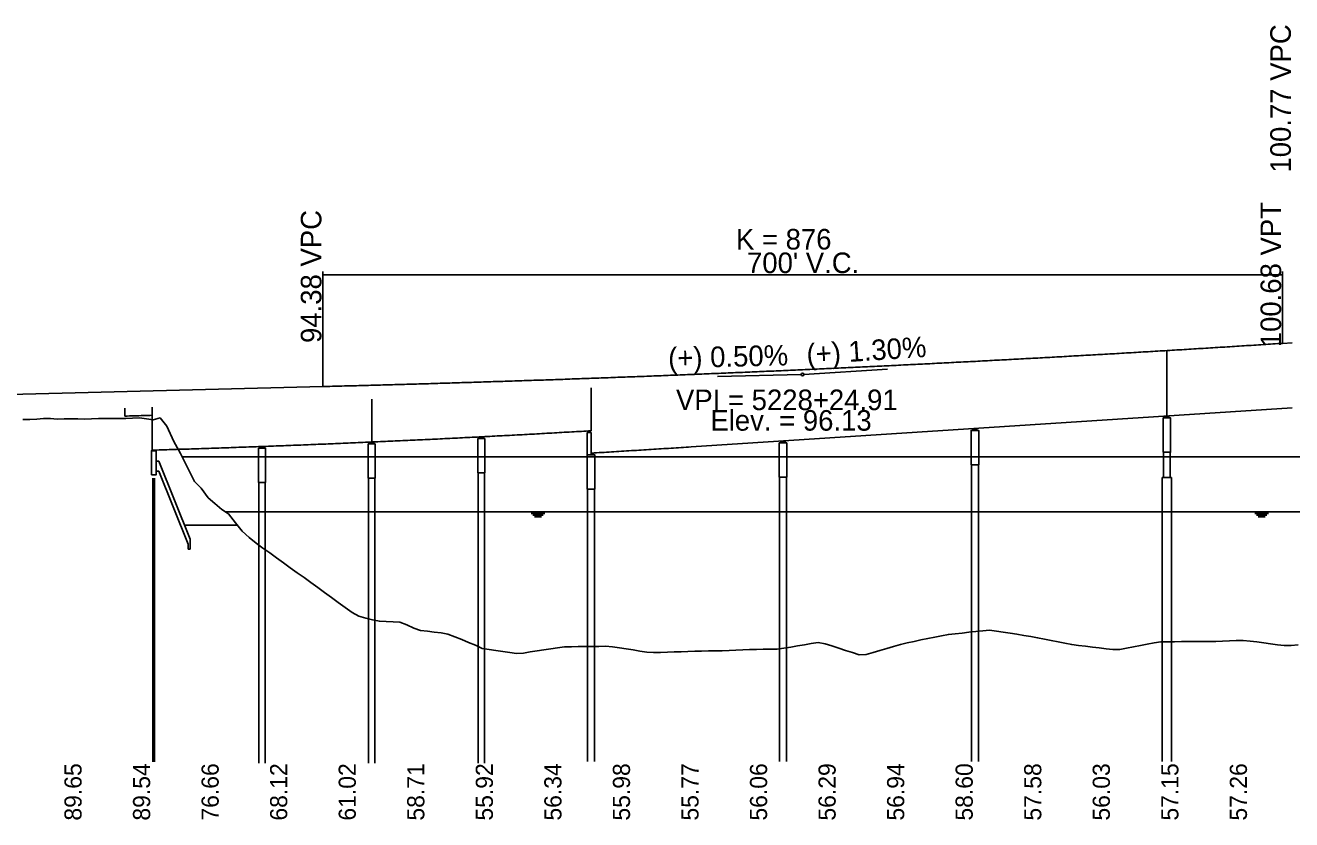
# Model space of a CAD drawing. Extents: x 2121671 to 2169879, y 557274 to 599957.
# Drawn here: x 2151826 to 2152750, y 595763 to 596343 of the extents above; entities that cross this region are included whole.
import ezdxf

# ---------------------------------------------------------------- set-up
doc = ezdxf.new("R2010")
doc.units = 0
for name, color, linetype in [('BR_CONCRETE', 7, 'Continuous'), ('BR_DETAILS', 7, 'Continuous'), ('BR_PRESTRESSED BEAM', 7, 'Continuous'), ('BR_STRUCTURAL STEEL', 7, 'Continuous'), ('RD_DDB_GradeTX', 7, 'Continuous'), ('RD_DDB_Profile_Elev', 7, 'Continuous'), ('RD_DDB_Profile_EX', 7, 'Continuous'), ('RD_DDB_Profile_Lbl', 7, 'Continuous'), ('RD_DDB_Profile_PR', 7, 'Continuous'), ('RD_DDB_StripGrade', 7, 'Continuous'), ('RD_DDB_VCLbl', 7, 'Continuous')]:
    doc.layers.add(name, color=color, linetype=linetype)

msp = doc.modelspace()

# ---------------------------------------------------------------- linework, layer by layer
at = {"layer": 'BR_CONCRETE'}
for p, q in [((2151898.82, 596063.63), (2151898.82, 596057.79)), ((2151898.82, 596063.63), (2151898.82, 596057.79)), ((2152236.07, 596029.6), (2152236.07, 596045.79)), ((2152236.07, 596045.79), (2152238.82, 596045.79)), ((2152236.07, 596029.6), (2152236.07, 596045.79)), ((2152236.07, 596045.79), (2152238.82, 596045.79)), ((2152238.82, 596045.79), (2152238.82, 596029.6)), ((2152238.82, 596045.79), (2152238.82, 596029.6)), ((2152656.32, 596031.43), (2152656.32, 596013.07)), ((2152656.32, 596031.43), (2152656.32, 596013.07)), ((2152661.32, 596031.43), (2152661.32, 596013.07)), ((2152661.32, 596031.43), (2152661.32, 596013.07)), ((2152516.32, 596022.33), (2152516.32, 596013.07)), ((2152516.32, 596022.33), (2152516.32, 596013.07)), ((2152521.32, 596022.33), (2152521.32, 596013.07)), ((2152521.32, 596022.33), (2152521.32, 596013.07)), ((2152076.57, 596012.55), (2152076.57, 595804.68)), ((2152076.57, 596012.55), (2152076.57, 595804.68)), ((2152081.07, 596012.55), (2152081.07, 595804.68)), ((2152081.07, 596012.55), (2152081.07, 595804.68)), ((2152156.57, 596016.35), (2152156.57, 595804.69)), ((2152156.57, 596016.35), (2152156.57, 595804.69)), ((2152161.07, 596016.35), (2152161.07, 595804.69)), ((2152161.07, 596016.35), (2152161.07, 595804.69)), ((2152376.32, 596013.23), (2152376.32, 596013.07)), ((2152376.32, 596013.23), (2152376.32, 596013.07)), ((2152376.32, 596013.07), (2152376.32, 595805.78)), ((2152376.32, 596013.07), (2152376.32, 595805.78)), ((2152381.32, 596013.23), (2152381.32, 596013.07)), ((2152381.32, 596013.23), (2152381.32, 596013.07)), ((2152381.32, 596013.07), (2152381.32, 595805.78)), ((2152381.32, 596013.07), (2152381.32, 595805.78)), ((2152516.32, 596013.07), (2152516.32, 595805.78)), ((2152516.32, 596013.07), (2152516.32, 595805.78)), ((2152521.32, 596013.07), (2152521.32, 595805.78)), ((2152521.32, 596013.07), (2152521.32, 595805.78)), ((2152655.32, 596013.07), (2152655.32, 595805.78)), ((2152655.32, 596013.07), (2152655.32, 595805.78)), ((2152662.32, 596013.07), (2152662.32, 595805.78)), ((2152662.32, 596013.07), (2152662.32, 595805.78)), ((2151996.57, 596009.32), (2151996.57, 595804.67)), ((2151996.57, 596009.32), (2151996.57, 595804.67)), ((2152001.07, 596009.32), (2152001.07, 595804.67)), ((2152001.07, 596009.32), (2152001.07, 595804.67)), ((2152236.32, 596004.6), (2152236.32, 595805.88)), ((2152236.32, 596004.6), (2152236.32, 595805.88)), ((2152241.32, 596004.6), (2152241.32, 595805.88)), ((2152241.32, 596004.6), (2152241.32, 595805.88))]:
    msp.add_line(p, q, dxfattribs=at)
for points in [[(2152656.07, 596031.43), (2152661.57, 596031.43), (2152661.57, 596056.43), (2152656.07, 596056.43)], [(2152656.07, 596031.43), (2152661.57, 596031.43), (2152661.57, 596056.43), (2152656.07, 596056.43)], [(2152156.32, 596016.35), (2152161.32, 596016.35), (2152161.32, 596041.35), (2152156.32, 596041.35)], [(2152156.32, 596016.35), (2152161.32, 596016.35), (2152161.32, 596041.35), (2152156.32, 596041.35)], [(2152516.07, 596022.33), (2152521.57, 596022.33), (2152521.57, 596047.33), (2152516.07, 596047.33)], [(2152516.07, 596022.33), (2152521.57, 596022.33), (2152521.57, 596047.33), (2152516.07, 596047.33)], [(2151918.16, 596015.05), (2151921.66, 596015.05), (2151921.66, 596032.55), (2151918.16, 596032.55)], [(2151918.16, 596015.05), (2151921.66, 596015.05), (2151921.66, 596032.55), (2151918.16, 596032.55)], [(2151996.32, 596009.32), (2152001.32, 596009.32), (2152001.32, 596034.32), (2151996.32, 596034.32)], [(2151996.32, 596009.32), (2152001.32, 596009.32), (2152001.32, 596034.32), (2151996.32, 596034.32)], [(2152076.32, 596012.55), (2152081.32, 596012.55), (2152081.32, 596037.55), (2152076.32, 596037.55)], [(2152076.32, 596012.55), (2152081.32, 596012.55), (2152081.32, 596037.55), (2152076.32, 596037.55)], [(2152236.07, 596004.6), (2152241.57, 596004.6), (2152241.57, 596029.6), (2152236.07, 596029.6)], [(2152236.07, 596004.6), (2152241.57, 596004.6), (2152241.57, 596029.6), (2152236.07, 596029.6)], [(2152376.07, 596013.23), (2152381.57, 596013.23), (2152381.57, 596038.23), (2152376.07, 596038.23)], [(2152376.07, 596013.23), (2152381.57, 596013.23), (2152381.57, 596038.23), (2152376.07, 596038.23)]]:
    msp.add_lwpolyline(points, close=True, dxfattribs=at)
msp.add_spline([(2151898.82, 596057.79), (2151905.74, 596057.99), (2151918.82, 596058.37)], degree=3, dxfattribs=at)
msp.add_spline([(2151898.82, 596057.79), (2151905.74, 596057.99), (2151918.82, 596058.37)], degree=3, dxfattribs=at)
at = {"layer": 'BR_DETAILS'}
for p, q in [((2151921.66, 596025.01), (2151923.66, 596025.01)), ((2151921.66, 596025.01), (2151923.66, 596025.01)), ((2151946.42, 595968.12), (2151923.66, 596025.01)), ((2151946.42, 595968.12), (2151923.66, 596025.01)), ((2151921.66, 596017.51), (2151923.66, 596017.51)), ((2151921.66, 596017.51), (2151923.66, 596017.51)), ((2151944.92, 595964.37), (2151923.66, 596017.51)), ((2151944.92, 595964.37), (2151923.66, 596017.51)), ((2151942.42, 595978.12), (2151980.88, 595978.12)), ((2151942.42, 595978.12), (2151980.88, 595978.12)), ((2151946.42, 595968.12), (2151946.42, 595960.62)), ((2151946.42, 595968.12), (2151946.42, 595960.62)), ((2151944.92, 595960.62), (2151944.92, 595964.37)), ((2151944.92, 595960.62), (2151944.92, 595964.37)), ((2151946.42, 595960.62), (2151944.92, 595960.62)), ((2151946.42, 595960.62), (2151944.92, 595960.62))]:
    msp.add_line(p, q, dxfattribs=at)
for points in [[(2152657.32, 596057.68), (2152658.32, 596057.68), (2152658.32, 596056.43), (2152657.32, 596056.43)], [(2152657.32, 596057.68), (2152658.32, 596057.68), (2152658.32, 596056.43), (2152657.32, 596056.43)], [(2152659.32, 596057.68), (2152660.32, 596057.68), (2152660.32, 596056.43), (2152659.32, 596056.43)], [(2152659.32, 596057.68), (2152660.32, 596057.68), (2152660.32, 596056.43), (2152659.32, 596056.43)], [(2152517.32, 596048.58), (2152518.32, 596048.58), (2152518.32, 596047.33), (2152517.32, 596047.33)], [(2152517.32, 596048.58), (2152518.32, 596048.58), (2152518.32, 596047.33), (2152517.32, 596047.33)], [(2152519.32, 596048.58), (2152520.32, 596048.58), (2152520.32, 596047.33), (2152519.32, 596047.33)], [(2152519.32, 596048.58), (2152520.32, 596048.58), (2152520.32, 596047.33), (2152519.32, 596047.33)], [(2152077.32, 596038.8), (2152078.32, 596038.8), (2152078.32, 596037.55), (2152077.32, 596037.55)], [(2152077.32, 596038.8), (2152078.32, 596038.8), (2152078.32, 596037.55), (2152077.32, 596037.55)], [(2152079.32, 596038.8), (2152080.32, 596038.8), (2152080.32, 596037.55), (2152079.32, 596037.55)], [(2152079.32, 596038.8), (2152080.32, 596038.8), (2152080.32, 596037.55), (2152079.32, 596037.55)], [(2152157.32, 596042.6), (2152158.32, 596042.6), (2152158.32, 596041.35), (2152157.32, 596041.35)], [(2152157.32, 596042.6), (2152158.32, 596042.6), (2152158.32, 596041.35), (2152157.32, 596041.35)], [(2152159.32, 596042.6), (2152160.32, 596042.6), (2152160.32, 596041.35), (2152159.32, 596041.35)], [(2152159.32, 596042.6), (2152160.32, 596042.6), (2152160.32, 596041.35), (2152159.32, 596041.35)], [(2152237.32, 596047.04), (2152238.32, 596047.04), (2152238.32, 596045.79), (2152237.32, 596045.79)], [(2152237.32, 596047.04), (2152238.32, 596047.04), (2152238.32, 596045.79), (2152237.32, 596045.79)], [(2152377.32, 596039.48), (2152378.32, 596039.48), (2152378.32, 596038.23), (2152377.32, 596038.23)], [(2152377.32, 596039.48), (2152378.32, 596039.48), (2152378.32, 596038.23), (2152377.32, 596038.23)], [(2152379.32, 596039.48), (2152380.32, 596039.48), (2152380.32, 596038.23), (2152379.32, 596038.23)], [(2152379.32, 596039.48), (2152380.32, 596039.48), (2152380.32, 596038.23), (2152379.32, 596038.23)], [(2151919.32, 596032.97), (2151920.49, 596032.97), (2151920.49, 596032.55), (2151919.32, 596032.55)], [(2151919.32, 596032.97), (2151920.49, 596032.97), (2151920.49, 596032.55), (2151919.32, 596032.55)], [(2151997.32, 596035.57), (2151998.32, 596035.57), (2151998.32, 596034.32), (2151997.32, 596034.32)], [(2151997.32, 596035.57), (2151998.32, 596035.57), (2151998.32, 596034.32), (2151997.32, 596034.32)], [(2151999.32, 596035.57), (2152000.32, 596035.57), (2152000.32, 596034.32), (2151999.32, 596034.32)], [(2151999.32, 596035.57), (2152000.32, 596035.57), (2152000.32, 596034.32), (2151999.32, 596034.32)], [(2152239.32, 596030.85), (2152240.32, 596030.85), (2152240.32, 596029.6), (2152239.32, 596029.6)], [(2152239.32, 596030.85), (2152240.32, 596030.85), (2152240.32, 596029.6), (2152239.32, 596029.6)]]:
    msp.add_lwpolyline(points, close=True, dxfattribs=at)
at = {"layer": 'BR_PRESTRESSED BEAM'}
for p, q in [((2152658.82, 596057.78), (2152658.82, 596105.28)), ((2152658.82, 596057.78), (2152658.82, 596105.28)), ((2152238.82, 596047.07), (2152238.82, 596078.32)), ((2152238.82, 596047.07), (2152238.82, 596078.32)), ((2152078.82, 596038.86), (2152078.82, 596070.11)), ((2152078.82, 596038.86), (2152078.82, 596070.11)), ((2151918.82, 596064.2), (2151918.82, 596032.95)), ((2151918.82, 596064.2), (2151918.82, 596032.95)), ((2152311.74, 596035.32), (2152750.24, 596063.82)), ((2152311.74, 596035.32), (2152750.24, 596063.82)), ((2152655.32, 596013.07), (2152662.32, 596013.07)), ((2152655.32, 596013.07), (2152662.32, 596013.07))]:
    msp.add_line(p, q, dxfattribs=at)
for points in [[(2151918.82, 596032.95), (2151920.24, 596032.99), (2151934.74, 596033.44), (2151949.24, 596033.9), (2151963.74, 596034.38), (2151978.24, 596034.88), (2151992.74, 596035.4), (2152007.24, 596035.94), (2152021.74, 596036.49), (2152036.24, 596037.07), (2152050.74, 596037.66), (2152065.24, 596038.27), (2152079.74, 596038.9), (2152094.24, 596039.55), (2152108.74, 596040.22), (2152123.24, 596040.91), (2152137.74, 596041.62), (2152152.24, 596042.34), (2152166.74, 596043.09), (2152181.24, 596043.85), (2152195.74, 596044.63), (2152210.24, 596045.44), (2152224.74, 596046.26), (2152238.82, 596047.07)], [(2151918.82, 596032.95), (2151920.24, 596032.99), (2151934.74, 596033.44), (2151949.24, 596033.9), (2151963.74, 596034.38), (2151978.24, 596034.88), (2151992.74, 596035.4), (2152007.24, 596035.94), (2152021.74, 596036.49), (2152036.24, 596037.07), (2152050.74, 596037.66), (2152065.24, 596038.27), (2152079.74, 596038.9), (2152094.24, 596039.55), (2152108.74, 596040.22), (2152123.24, 596040.91), (2152137.74, 596041.62), (2152152.24, 596042.34), (2152166.74, 596043.09), (2152181.24, 596043.85), (2152195.74, 596044.63), (2152210.24, 596045.44), (2152224.74, 596046.26), (2152238.82, 596047.07)], [(2152238.82, 596030.82), (2152239.24, 596030.84), (2152253.74, 596031.7), (2152268.24, 596032.58), (2152282.74, 596033.47), (2152297.24, 596034.39), (2152311.74, 596035.32)], [(2152238.82, 596030.82), (2152239.24, 596030.84), (2152253.74, 596031.7), (2152268.24, 596032.58), (2152282.74, 596033.47), (2152297.24, 596034.39), (2152311.74, 596035.32)]]:
    msp.add_spline(points, degree=3, dxfattribs=at)
at = {"layer": 'BR_STRUCTURAL STEEL'}
for p, q in [((2151919.32, 596012.51), (2151919.32, 595805.58)), ((2151919.32, 596012.51), (2151919.32, 595805.58)), ((2151920.49, 596012.51), (2151920.49, 595805.58)), ((2151920.49, 596012.51), (2151920.49, 595805.58))]:
    msp.add_line(p, q, dxfattribs=at)
at = {"layer": 'RD_DDB_GradeTX'}
for p, q in [((2152331.17, 596086.57), (2152392.16, 596088.09)), ((2152455.02, 596092.14), (2152394.15, 596088.18))]:
    msp.add_line(p, q, dxfattribs=at)
msp.add_circle((2152393.15, 596088.12), 1, dxfattribs=at)
at = {"layer": 'RD_DDB_Profile_Elev'}
for p, q in [((2151940.69, 596028.07), (2155629.71, 596028.07)), ((2151971.97, 595988.07), (2156334.94, 595988.07)), ((2152195.16, 595986.82), (2152205.16, 595986.82)), ((2152196.41, 595985.57), (2152203.91, 595985.57)), ((2152197.66, 595984.32), (2152202.66, 595984.32)), ((2152723, 595986.82), (2152733, 595986.82)), ((2152724.25, 595985.57), (2152731.75, 595985.57)), ((2152725.5, 595984.32), (2152730.5, 595984.32))]:
    msp.add_line(p, q, dxfattribs=at)
at = {"layer": 'RD_DDB_Profile_EX'}
for points in [[(2151824.48, 596055.23), (2151829.48, 596055.31), (2151834.48, 596055.57), (2151839.48, 596055.98), (2151844.48, 596055.98), (2151849.48, 596055.53), (2151854.48, 596055.69), (2151859.48, 596055.83), (2151864.48, 596055.79), (2151869.48, 596055.67), (2151874.48, 596055.78), (2151879.48, 596055.97), (2151884.48, 596056.16), (2151889.48, 596055.98), (2151894.48, 596056.08), (2151899.48, 596056.01), (2151904.48, 596056.23), (2151909.48, 596056.55), (2151914.48, 596055.74), (2151919.48, 596054.96), (2151924.48, 596056.45), (2151929.48, 596050.33), (2151934.48, 596039.19), (2151939.48, 596030.54), (2151944.48, 596020.27), (2151949.48, 596010.09), (2151954.48, 596005.12), (2151959.48, 595998.24), (2151964.48, 595993.98), (2151969.48, 595989.72), (2151974.48, 595986.4), (2151979.48, 595979.81), (2151984.48, 595973.75), (2151989.48, 595969.33), (2151994.48, 595964.99), (2151999.48, 595961.56), (2152004.48, 595958.03), (2152009.48, 595954.42), (2152014.48, 595950.8), (2152019.48, 595947.18), (2152024.48, 595943.57), (2152029.48, 595939.95), (2152034.48, 595936.33), (2152039.48, 595932.72), (2152044.48, 595929.1), (2152049.48, 595925.48), (2152054.48, 595921.87), (2152059.48, 595918.25), (2152064.48, 595914.63), (2152069.48, 595911.89), (2152074.48, 595910.47), (2152079.48, 595909.05), (2152084.48, 595908.12), (2152089.48, 595907.89), (2152094.48, 595907.67), (2152099.48, 595907.44), (2152104.48, 595905.51), (2152109.48, 595903.15), (2152114.48, 595901.46), (2152119.48, 595900.87), (2152124.48, 595900.28), (2152129.48, 595899.69), (2152134.48, 595898.75), (2152139.48, 595896.73), (2152144.48, 595894.72), (2152149.48, 595892.7), (2152154.48, 595890.68), (2152159.48, 595888.34), (2152164.48, 595887.61), (2152169.48, 595886.88), (2152174.48, 595886.16), (2152179.48, 595885.43), (2152184.48, 595884.7), (2152189.48, 595884.95), (2152194.48, 595885.72)], [(2152194.48, 595885.72), (2152199.48, 595886.45), (2152204.48, 595887.17), (2152209.48, 595887.9), (2152214.48, 595888.63), (2152219.48, 595889.35), (2152224.48, 595889.55), (2152229.48, 595889.62), (2152234.48, 595889.69), (2152239.48, 595889.76), (2152244.48, 595889.83), (2152249.48, 595889.85), (2152254.48, 595889.53), (2152259.48, 595888.74), (2152264.48, 595887.96), (2152269.48, 595887.18), (2152274.48, 595886.39), (2152279.48, 595885.61), (2152284.48, 595885.25), (2152289.48, 595885.4), (2152294.48, 595885.56), (2152299.48, 595885.71), (2152304.48, 595885.86), (2152309.48, 595886.01), (2152314.48, 595886.24), (2152319.48, 595886.34), (2152324.48, 595886.45), (2152329.48, 595886.55), (2152334.48, 595886.65), (2152339.48, 595886.75), (2152344.48, 595887.11), (2152349.48, 595887.26), (2152354.48, 595887.4), (2152359.48, 595887.53), (2152364.48, 595887.67), (2152369.48, 595887.81), (2152374.48, 595887.85), (2152379.48, 595888.5), (2152384.48, 595889.33), (2152389.48, 595890.16), (2152394.48, 595890.99), (2152399.48, 595891.83), (2152404.48, 595892.66), (2152409.48, 595891.76), (2152414.48, 595890.14), (2152419.48, 595888.53), (2152424.48, 595886.91), (2152429.48, 595885.3), (2152434.48, 595883.68), (2152439.48, 595883.95), (2152444.48, 595885.42), (2152449.48, 595886.88), (2152454.48, 595888.35), (2152459.48, 595889.81), (2152464.48, 595891.28), (2152469.48, 595892.44), (2152474.48, 595893.47), (2152479.48, 595894.5), (2152484.48, 595895.53), (2152489.48, 595896.55), (2152494.48, 595897.58), (2152499.48, 595898.49), (2152504.48, 595899.01), (2152509.48, 595899.54), (2152514.48, 595900.06), (2152519.48, 595900.58), (2152524.48, 595901.1), (2152529.48, 595901.63), (2152534.48, 595900.95), (2152539.48, 595900.17), (2152544.48, 595899.38), (2152549.48, 595898.6), (2152554.48, 595897.81), (2152559.48, 595897.03), (2152564.48, 595896.1), (2152569.48, 595895.1), (2152574.48, 595894.11), (2152579.48, 595893.12), (2152584.48, 595892.13), (2152589.48, 595891.13), (2152594.48, 595890.43), (2152599.48, 595889.84), (2152604.48, 595889.24), (2152609.48, 595888.64), (2152614.48, 595888.04), (2152619.48, 595887.45), (2152624.48, 595887.51), (2152629.48, 595888.46), (2152634.48, 595889.41), (2152639.48, 595890.37), (2152644.48, 595891.32), (2152649.48, 595892.27), (2152654.48, 595893.14), (2152659.48, 595893.17), (2152664.48, 595893.21), (2152669.48, 595893.24), (2152674.48, 595893.27), (2152679.48, 595893.3), (2152684.48, 595893.3), (2152689.48, 595893.28), (2152694.48, 595893.46)], [(2152694.48, 595893.46), (2152699.48, 595893.63), (2152704.48, 595893.81), (2152709.48, 595893.98), (2152714.48, 595894.16), (2152719.48, 595893.66), (2152724.48, 595893), (2152729.48, 595892.34), (2152734.48, 595891.68), (2152739.48, 595891.02), (2152744.48, 595890.36), (2152749.48, 595890.41), (2152754.48, 595890.85)]]:
    msp.add_lwpolyline(points, dxfattribs=at)
at = {"layer": 'RD_DDB_Profile_PR'}
for p, q in [((2152743.15, 596110.87), (2152750.24, 596111.33)), ((2151239.77, 596059.26), (2152043.15, 596079.36))]:
    msp.add_line(p, q, dxfattribs=at)
msp.add_spline([(2152043.15, 596079.36), (2152057.15, 596079.72), (2152071.15, 596080.08), (2152085.15, 596080.46), (2152099.15, 596080.85), (2152113.15, 596081.25), (2152127.15, 596081.66), (2152141.15, 596082.09), (2152155.15, 596082.52), (2152169.15, 596082.97), (2152183.15, 596083.42), (2152197.15, 596083.89), (2152211.15, 596084.37), (2152225.15, 596084.86), (2152239.15, 596085.36), (2152253.15, 596085.88), (2152267.15, 596086.4), (2152281.15, 596086.93), (2152295.15, 596087.48), (2152309.15, 596088.04), (2152323.15, 596088.61), (2152337.15, 596089.19), (2152351.15, 596089.78), (2152365.15, 596090.38), (2152379.15, 596090.99), (2152393.15, 596091.62), (2152407.15, 596092.25), (2152421.15, 596092.9), (2152435.15, 596093.56), (2152449.15, 596094.23), (2152463.15, 596094.91), (2152477.15, 596095.6), (2152491.15, 596096.3), (2152505.15, 596097.02), (2152519.15, 596097.74), (2152533.15, 596098.48), (2152547.15, 596099.23), (2152561.15, 596099.98), (2152575.15, 596100.75), (2152589.15, 596101.54), (2152603.15, 596102.33), (2152617.15, 596103.13), (2152631.15, 596103.95), (2152645.15, 596104.77), (2152659.15, 596105.61), (2152673.15, 596106.46), (2152687.15, 596107.32), (2152701.15, 596108.19), (2152715.15, 596109.07), (2152729.15, 596109.96), (2152743.15, 596110.87)], degree=3, dxfattribs=at)
at = {"layer": 'RD_DDB_VCLbl'}
for p, q in [((2152043.15, 596163.37), (2152043.15, 596079.36)), ((2152043.15, 596160.87), (2152743.15, 596160.87)), ((2152743.15, 596163.37), (2152743.15, 596110.87))]:
    msp.add_line(p, q, dxfattribs=at)

# ---------------------------------------------------------------- texts
at = {"layer": 'RD_DDB_GradeTX'}
for s, rotation, p in [('(+) 1.30%', 3.71869, (2152396.46, 596095.3)), ('(+) 0.50%', 1.43336, (2152295.24, 596092.63))]:
    msp.add_text(s, height=15, rotation=rotation, dxfattribs=at).set_placement(p)
at = {"layer": 'RD_DDB_Profile_Lbl'}
for s, p in [('VPI = 5228+24.91', (2152300.79, 596062.16)), ('Elev. = 96.13', (2152325.86, 596047.16))]:
    msp.add_text(s, height=15, dxfattribs=at).set_placement(p)
at = {"layer": 'RD_DDB_StripGrade'}
for s, height, p in [('100.77 VPC', 15, (2152749.24, 596235.47)), ('94.38 VPC', 15, (2152042.15, 596111.14)), ('100.68 VPT', 15, (2152742.15, 596108.04)), ('89.65', 12.5, (2151867.24, 595762.7)), ('89.54', 12.5, (2151917.24, 595762.7)), ('76.66', 12.5, (2151967.24, 595762.7)), ('68.12', 12.5, (2152017.24, 595762.7)), ('61.02', 12.5, (2152067.24, 595762.7)), ('58.71', 12.5, (2152117.24, 595762.7)), ('55.92', 12.5, (2152167.24, 595762.7)), ('56.34', 12.5, (2152217.24, 595762.7)), ('55.98', 12.5, (2152267.24, 595762.7)), ('55.77', 12.5, (2152317.24, 595762.7)), ('56.06', 12.5, (2152367.24, 595762.7)), ('56.29', 12.5, (2152417.24, 595762.7)), ('56.94', 12.5, (2152467.24, 595762.7)), ('58.60', 12.5, (2152517.24, 595762.7)), ('57.58', 12.5, (2152567.24, 595762.7)), ('56.03', 12.5, (2152617.24, 595762.7)), ('57.15', 12.5, (2152667.24, 595762.7)), ('57.26', 12.5, (2152717.24, 595762.7))]:
    msp.add_text(s, height=height, rotation=90, dxfattribs=at).set_placement(p)
at = {"layer": 'RD_DDB_VCLbl'}
for s, p in [('K = 876', (2152344.51, 596179.33)), ("700' V.C.", (2152352.6, 596162.12))]:
    msp.add_text(s, height=15, dxfattribs=at).set_placement(p)

doc.saveas('drawing.dxf')
